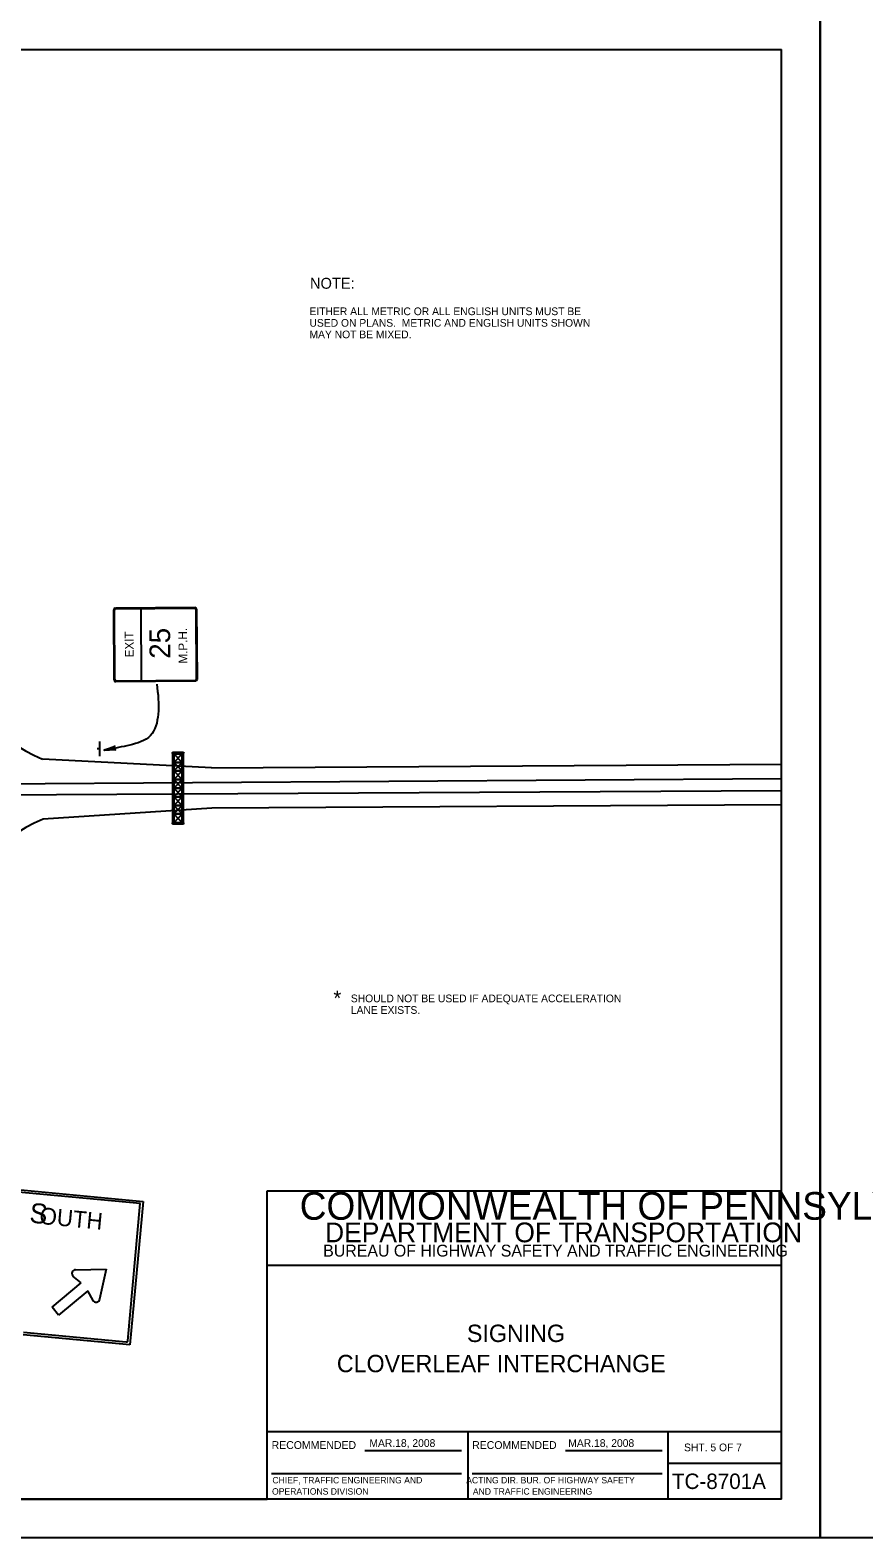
# Model space of a CAD drawing. Extents: x 640994 to 644422, y 298458 to 299646.
# Drawn here: x 641528 to 641852, y 298458 to 299044 of the extents above; entities that cross this region are included whole.
import ezdxf

# ---------------------------------------------------------------- set-up
doc = ezdxf.new("R2010")
doc.units = 0
for name, color, linetype in [('1', 7, 'Continuous'), ('2', 7, 'Continuous'), ('PLT-BNDY', 7, 'Continuous'), ('XCS-GRID-MIN', 7, 'Continuous')]:
    doc.layers.add(name, color=color, linetype=linetype)

msp = doc.modelspace()

# ---------------------------------------------------------------- linework, layer by layer
at = {"layer": '1'}
for p, q in [((641034.31, 299036.63), (641820.31, 299036.63)), ((641820.31, 298472.63), (641820.31, 299036.63)), ((641620.31, 298472.63), (641620.31, 298592.63)), ((641620.31, 298592.63), (641820.31, 298592.63)), ((641820.31, 298563.63), (641620.31, 298563.63)), ((641620.31, 298499), (641820.31, 298499)), ((641698.31, 298499), (641698.31, 298472.63)), ((641776.19, 298472.63), (641776.19, 298499)), ((641658.24, 298491.57), (641695.87, 298491.57)), ((641736.24, 298491.57), (641773.87, 298491.57)), ((641621.99, 298482.68), (641695.87, 298482.68)), ((641699.99, 298482.68), (641773.87, 298482.68)), ((641776.19, 298486.63), (641820.31, 298486.63)), ((641820.31, 298472.63), (641034.31, 298472.63)), ((641034.31, 298472.63), (641620.31, 298472.63))]:
    msp.add_line(p, q, dxfattribs=at)
at = {"layer": '2'}
for p, q in [((641560.69, 298791.38), (641560.56, 298818.63)), ((641560.94, 298791.5), (641560.81, 298818.38)), ((641561.19, 298819.38), (641592.19, 298819.63)), ((641561.31, 298819), (641591.94, 298819.25)), ((641571.31, 298791), (641571.19, 298819.13)), ((641592.56, 298818.63), (641592.69, 298791.75)), ((641592.81, 298818.88), (641593.06, 298791.5)), ((641592.44, 298790.88), (641561.31, 298790.63)), ((641592.19, 298791.13), (641561.56, 298790.88)), ((641555.06, 298764.5), (641554.06, 298764.5)), ((641555.06, 298767.38), (641555.06, 298761.75)), ((641598.56, 298757.13), (641532.94, 298760.5)), ((641583.94, 298762.63), (641587.19, 298759.25)), ((641587.19, 298762.63), (641583.94, 298759.25)), ((641583.94, 298759.25), (641587.19, 298756)), ((641587.19, 298759.25), (641583.94, 298756)), ((641598.56, 298757.13), (641820.31, 298758.53)), ((641820.31, 298752.92), (641403.56, 298750.13)), ((641583.94, 298756), (641587.19, 298752.63)), ((641587.19, 298756), (641583.94, 298752.63)), ((641583.94, 298752.63), (641587.19, 298749.25)), ((641587.19, 298752.63), (641583.94, 298749.25)), ((641403.06, 298746), (641820.31, 298748.39)), ((641583.94, 298749.25), (641587.19, 298745.88)), ((641587.19, 298749.25), (641583.94, 298745.88)), ((641583.94, 298745.88), (641587.19, 298742.5)), ((641587.19, 298745.88), (641583.94, 298742.5)), ((641598.69, 298741.5), (641533.06, 298737.25)), ((641583.94, 298742.5), (641587.19, 298739.25)), ((641587.19, 298742.5), (641583.94, 298739.25)), ((641820.31, 298742.77), (641598.69, 298741.5)), ((641583.94, 298739.25), (641587.19, 298735.75)), ((641587.19, 298739.25), (641583.94, 298735.75)), ((641587.19, 298735.75), (641587.19, 298739.25)), ((641482.95, 298596.91), (641572.07, 298588.42)), ((641566.07, 298534.29), (641570.89, 298587.75)), ((641572.07, 298588.42), (641566.82, 298532.67)), ((641547.95, 298556.79), (641544.7, 298559.42)), ((641545.7, 298561.92), (641557.57, 298562.17)), ((641557.57, 298562.17), (641555.07, 298550.42)), ((641536.57, 298547.42), (641547.95, 298556.79)), ((641550.45, 298553.67), (641539.07, 298544.29)), ((641552.57, 298549.92), (641550.45, 298553.67)), ((641539.07, 298544.29), (641536.57, 298547.42)), ((641566.82, 298532.67), (641525.37, 298536.61)), ((641525.47, 298537.63), (641565.45, 298533.92))]:
    msp.add_line(p, q, dxfattribs=at)
for points in [[(641561.03, 298764.34), (641560.78, 298764.59), (641556.9, 298764.09), (641561.03, 298764.34), (641561.28, 298764.21), (641556.9, 298764.09), (641560.78, 298764.96), (641560.78, 298765.21), (641556.9, 298764.09), (641561.03, 298765.59), (641560.78, 298765.21)], [(641587.19, 298763.13), (641583.94, 298763.13)], [(641583.44, 298762.63), (641583.44, 298735.75)], [(641583.94, 298735.75), (641587.19, 298735.75), (641587.19, 298762.63), (641583.94, 298762.63), (641583.94, 298735.75)], [(641587.69, 298735.75), (641587.69, 298762.63)], [(641583.94, 298735.38), (641587.19, 298735.38)], [(641570.89, 298587.75), (641484.32, 298595.67)]]:
    msp.add_lwpolyline(points, dxfattribs=at)
for points in [[(641583.94, 298759.25), (641583.94, 298762.63), (641587.19, 298762.63), (641587.19, 298759.25)], [(641583.94, 298756), (641583.94, 298759.25), (641587.19, 298759.25), (641587.19, 298756)], [(641583.94, 298752.63), (641583.94, 298756), (641587.19, 298756), (641587.19, 298752.63)], [(641583.94, 298749.25), (641583.94, 298752.63), (641587.19, 298752.63), (641587.19, 298749.25)], [(641583.94, 298745.88), (641583.94, 298749.25), (641587.19, 298749.25), (641587.19, 298745.88)], [(641583.94, 298742.5), (641583.94, 298745.88), (641587.19, 298745.88), (641587.19, 298742.5)], [(641583.94, 298739.25), (641583.94, 298742.5), (641587.19, 298742.5), (641587.19, 298739.25)], [(641583.94, 298735.75), (641583.94, 298739.25), (641587.19, 298739.25), (641587.19, 298735.75)]]:
    msp.add_lwpolyline(points, close=True, dxfattribs=at)
for centre in [(641583.7, 298762.91), (641587.48, 298762.91), (641583.7, 298735.61), (641587.48, 298735.61)]:
    msp.add_circle(centre, 0.301, dxfattribs=at)
for centre, radius, start, end in [((641555.3, 298815.87), 59.66, 191.54204, 247.96006), ((641556.17, 298682.23), 59.66, 112.7883, 169.20632), ((641570.38, 298587.12), 0.528, 354.14399, 84.50768), ((641545.72, 298560.49), 1.4, 89.42516, 230.09068), ((641553.72, 298550.69), 1.4, 207.81363, 351.72026), ((641565.52, 298534.36), 0.528, 264.80557, 354.95755)]:
    msp.add_arc(centre, radius, start, end, dxfattribs=at)
for centre, major_axis, start_param, end_param in [((641561.19, 298818.62), (0.005, -0.717), 3.141593, 4.712389), ((641561.38, 298818.41), (0.004, -0.657), 3.141593, 4.712389), ((641591.98, 298818.61), (-0.004, 0.657), 4.712389, 6.283185), ((641592.17, 298818.82), (-0.005, 0.717), 4.712389, 6.283185), ((641561.37, 298791.37), (0.005, -0.717), 4.712389, 6.283185), ((641561.56, 298791.58), (0.004, -0.657), 4.712389, 6.283185), ((641592.15, 298791.78), (-0.004, 0.657), 3.141593, 4.712389), ((641592.34, 298791.58), (0.005, -0.717), 0, 1.570796)]:
    msp.add_ellipse(centre, major_axis=major_axis, ratio=0.9, start_param=start_param, end_param=end_param, dxfattribs=at)
msp.add_spline([(641577.3, 298789.76), (641577.85, 298777.96), (641574.82, 298769.72), (641566.77, 298766), (641558.15, 298764.3)], degree=3, dxfattribs=at)
at = {"layer": 'XCS-GRID-MIN'}
for points in [[(640994.31, 299051.63), (641835.31, 299051.63), (641835.31, 298457.63), (640994.31, 298457.63)], [(641835.31, 299051.63), (642676.31, 299051.63), (642676.31, 298457.63), (641835.31, 298457.63)]]:
    msp.add_lwpolyline(points, close=True, dxfattribs=at)

# ---------------------------------------------------------------- texts
at = {"layer": '1'}
for s, height, p in [('COMMONWEALTH OF PENNSYLVANIA', 10.7828, (641632.9, 298581.36)), ('DEPARTMENT OF TRANSPORTATION', 7.6837, (641642.76, 298572.61)), ('BUREAU OF HIGHWAY SAFETY AND TRAFFIC ENGINEERING', 4.6253, (641642.04, 298567.04)), ('SIGNING', 6.75, (641697.96, 298533.81)), ('CLOVERLEAF INTERCHANGE', 6.75, (641647.36, 298522.06)), ('RECOMMENDED', 3.048, (641621.99, 298492.2)), ('RECOMMENDED', 3.048, (641699.99, 298492.2)), ('SHT. 5 OF 7', 3, (641782.4, 298491.31)), ('TC-8701A', 6, (641777.68, 298476.63))]:
    msp.add_text(s, height=height, dxfattribs=at).set_placement(p)
at = {"layer": '2'}
for s, height, p in [('NOTE:', 4.25, (641636.91, 298943.53)), ('EITHER ALL METRIC OR ALL ENGLISH UNITS MUST BE', 3, (641636.7, 298933.26)), ('USED ON PLANS.  METRIC AND ENGLISH UNITS SHOWN', 3, (641636.7, 298928.76)), ('MAY NOT BE MIXED.', 3, (641636.7, 298924.26)), ('*', 5.85, (641646.02, 298664.66)), ('SHOULD NOT BE USED IF ADEQUATE ACCELERATION', 3, (641652.79, 298665.97)), ('LANE EXISTS.', 3, (641652.79, 298661.47)), ('MAR.18, 2008', 3, (641660.01, 298493)), ('MAR.18, 2008', 3, (641737.36, 298493))]:
    msp.add_text(s, height=height, dxfattribs=at).set_placement(p)
for s, height, rotation, p in [('EXIT', 3.387, 90.3745, (641568.31, 298800.13)), ('25', 8.061, 90.37458, (641582.56, 298799.63)), ('M.P.H.', 3.387, 90.37456, (641589.19, 298797.75)), ('35', 0.0217, 90, (641572.56, 298800.88)), ('S', 7.75, 354.58165, (641527.57, 298580.29)), ('OUTH', 6.5, 354.56831, (641531.45, 298579.79))]:
    msp.add_text(s, height=height, rotation=rotation, dxfattribs=at).set_placement(p)
at = {"layer": 'PLT-BNDY'}
for s, p in [('OPERATIONS DIVISION', (641622.14, 298474.44)), ('CHIEF, TRAFFIC ENGINEERING AND', (641622.28, 298478.81)), ('  ACTING DIR. BUR. OF HIGHWAY SAFETY', (641695.81, 298478.8)), ('  ACTING DIR. BUR. OF HIGHWAY SAFETY', (641695.81, 298478.8))]:
    msp.add_text(s, height=2.5, dxfattribs=at).set_placement(p)
msp.add_text('AND TRAFFIC ENGINEERING', height=2.5, rotation=360, dxfattribs=at).set_placement((641700.25, 298474.43))
msp.add_text('AND TRAFFIC ENGINEERING', height=2.5, rotation=360, dxfattribs=at).set_placement((641700.25, 298474.43))

doc.saveas('drawing.dxf')
